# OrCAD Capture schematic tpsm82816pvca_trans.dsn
size D; title: TPSM82816PVCA: 6V 6A step down module; rev: 1.0; note: Datasheet: SLUSEY7B     EVM: SLUUD40; note: Synchronous Step Down Converter
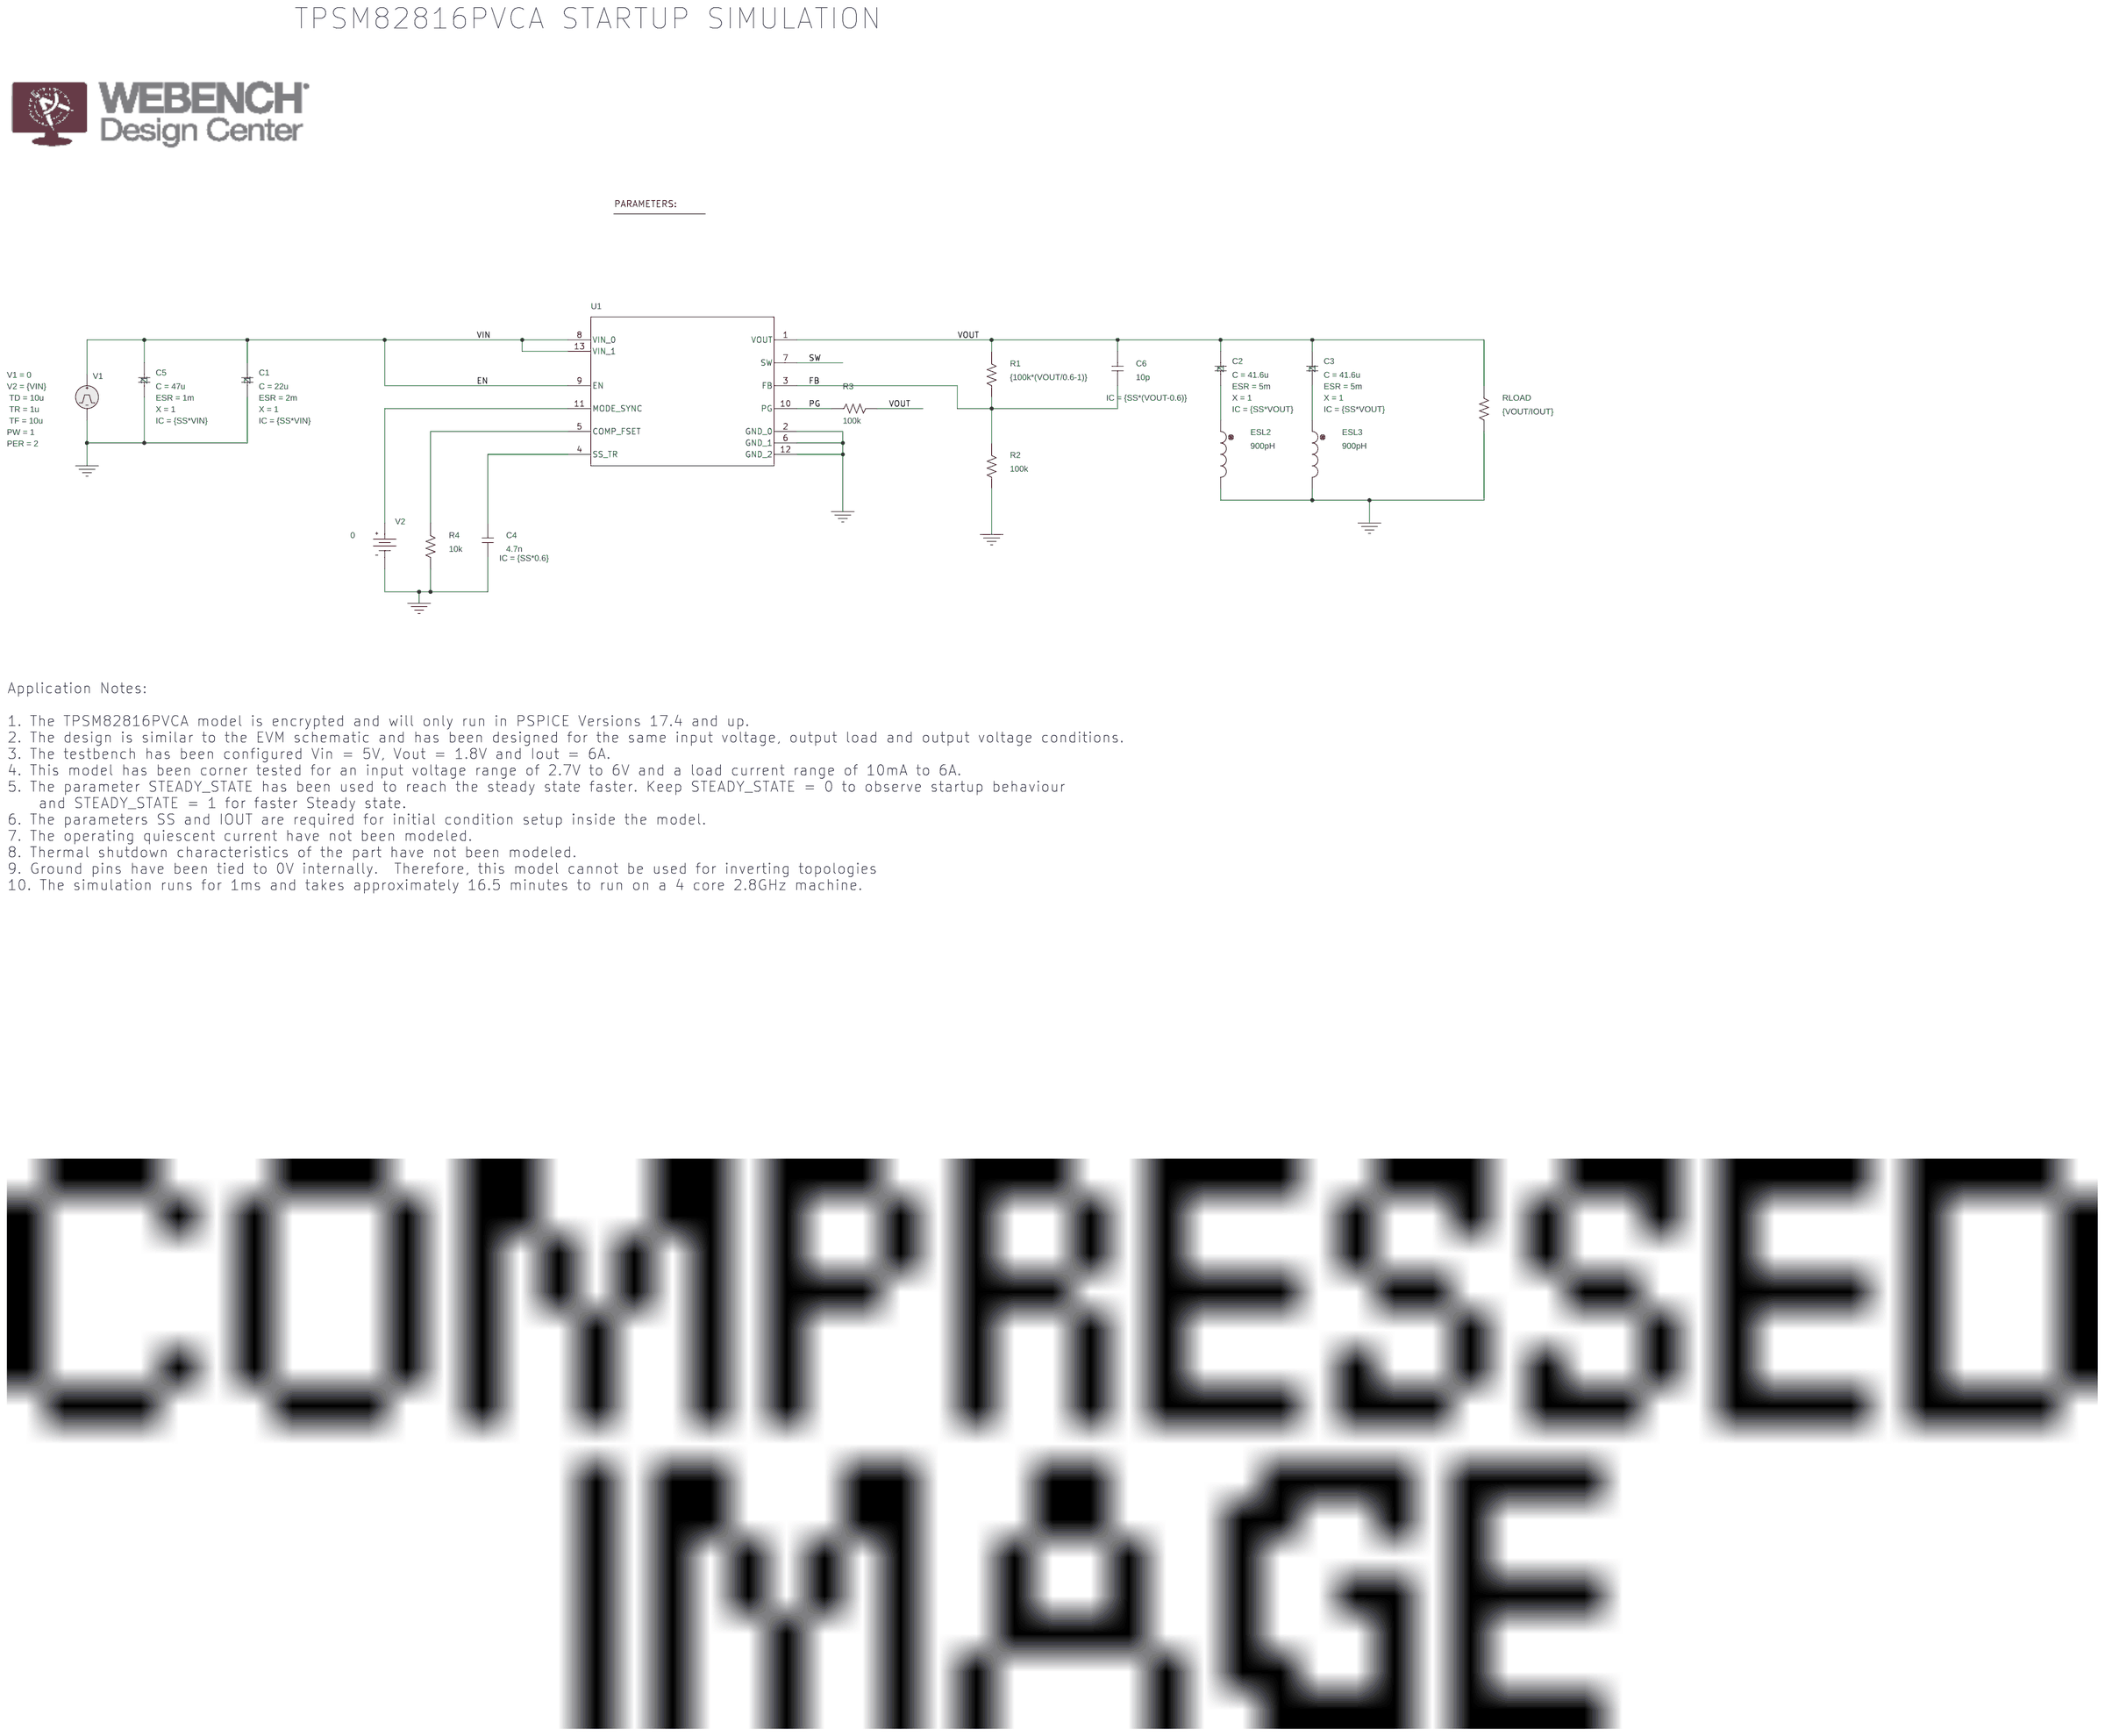
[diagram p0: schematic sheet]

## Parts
2  PARAM
C1  CESR
C2  CESR
C3  CESR
C4  4.7n  [RAD/CK05]
C5  CESR
C6  10p  [RAD/CK05]
ESL2  900pH  [DISC350x175LS200x100034]
ESL3  900pH  [DISC350x175LS200x100034]
R1  {100k*(VOUT/0.6-1)}  [AX/RC05]
R2  100k  [AX/RC05]
R3  100k  [AX/RC05]
R4  10k  [AX/RC05]
RLOAD  {VOUT/IOUT}  [AX/RC05]
U1  TPSM82816PVCA_TRANS  [VCA0013A-MFG]
V1  VPULSE
V2  VDC

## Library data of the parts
2 = PARAM: IOUT: 6; SS: 0; VIN: 5; VOUT: 1.8
C1 = CESR_1: C: 22u; ESR: 2m; IC: {SS*VIN}; PSpiceTemplate: X^@REFDES %1 %2 @MODEL PARAMS: ?C|C=@C||C=10U| ?ESR|ESR=@ESR||ESR=2M| ?IC|IC=@IC||IC=0| ?X|X=@X||X=0|; X: 1
C2 = CESR_1_3: C: 41.6u; ESR: 5m; IC: {SS*VOUT}; PSpiceTemplate: X^@REFDES %1 %2 @MODEL PARAMS: ?C|C=@C||C=10U| ?ESR|ESR=@ESR||ESR=2M| ?IC|IC=@IC||IC=0| ?X|X=@X||X=0|; X: 1
C3 = CESR_1_2: C: 41.6u; ESR: 5m; IC: {SS*VOUT}; PSpiceTemplate: X^@REFDES %1 %2 @MODEL PARAMS: ?C|C=@C||C=10U| ?ESR|ESR=@ESR||ESR=2M| ?IC|IC=@IC||IC=0| ?X|X=@X||X=0|; X: 1
C4 = C: IC: {SS*0.6}
C5 = CESR_1_1: C: 47u; ESR: 1m; IC: {SS*VIN}; PSpiceTemplate: X^@REFDES %1 %2 @MODEL PARAMS: ?C|C=@C||C=10U| ?ESR|ESR=@ESR||ESR=2M| ?IC|IC=@IC||IC=0| ?X|X=@X||X=0|; X: 1
C6 = C: IC: {SS*(VOUT-0.6)}
ESL2 ESL3 = L
R1-R4 RLOAD = R
U1 = TPSM82816PVCA_TRANS
V1 = VPULSE: PER: 2; PW: 1; TD: 10u; TF: 10u; TR: 1u; V1: 0; V2: {VIN}
V2 = VDC: DC: 0

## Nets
0: C1.2 C4.2 C5.2 ESL2.2 ESL3.2 R2.2 R4.2 RLOAD.2 U1.2(GND_0) U1.6(GND_1) U1.12(GND_2) V1.2(-) V2.1(-)
EN: C1.1 C5.1 U1.8(VIN_0) U1.9(EN) U1.13(VIN_1) V1.1(+)
FB: C6.2 R1.2 R2.1 U1.3(FB)
PG: R3.1 U1.10(PG)
SW: U1.7(SW)
VOUT: C2.1 C3.1 C6.1 R1.1 R3.2 RLOAD.1 U1.1(VOUT)
N16777530: C2.2 ESL2.1
N16777532: C3.2 ESL3.1
N16777564: U1.11(MODE_SYNC) V2.0(+)
N16777597: R4.1 U1.5(COMP_FSET)
N16777654: C4.1 U1.4(SS_TR)

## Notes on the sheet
- TPSM82816PVCA STARTUP SIMULATION
- Application Notes:
  1. The TPSM82816PVCA model is encrypted and will only run in PSPICE Versions 17.4 and up.
  2. The design is similar to the EVM schematic and has been designed for the same input voltage, output load and output voltage conditions.
  3. The testbench has been configured Vin = 5V, Vout = 1.8V and Iout = 6A.
  4. This model has been corner tested for an input voltage range of 2.7V to 6V and a load current range of 10mA to 6A.
  5. The parameter STEADY_STATE has been used to reach the steady state faster. Keep STEADY_STATE = 0 to observe startup behaviour
      and STEADY_STATE = 1 for faster Steady state.
  6. The parameters SS and IOUT are required for initial condition setup inside the model.
  7. The operating quiescent current have not been modeled.
  8. Thermal shutdown characteristics of the part have not been modeled.
  9. Ground pins have been tied to 0V internally.  Therefore, this model cannot be used for inverting topologies
  10. The simulation runs for 1ms and takes approximately 16.5 minutes to run on a 4 core 2.8GHz machine.
